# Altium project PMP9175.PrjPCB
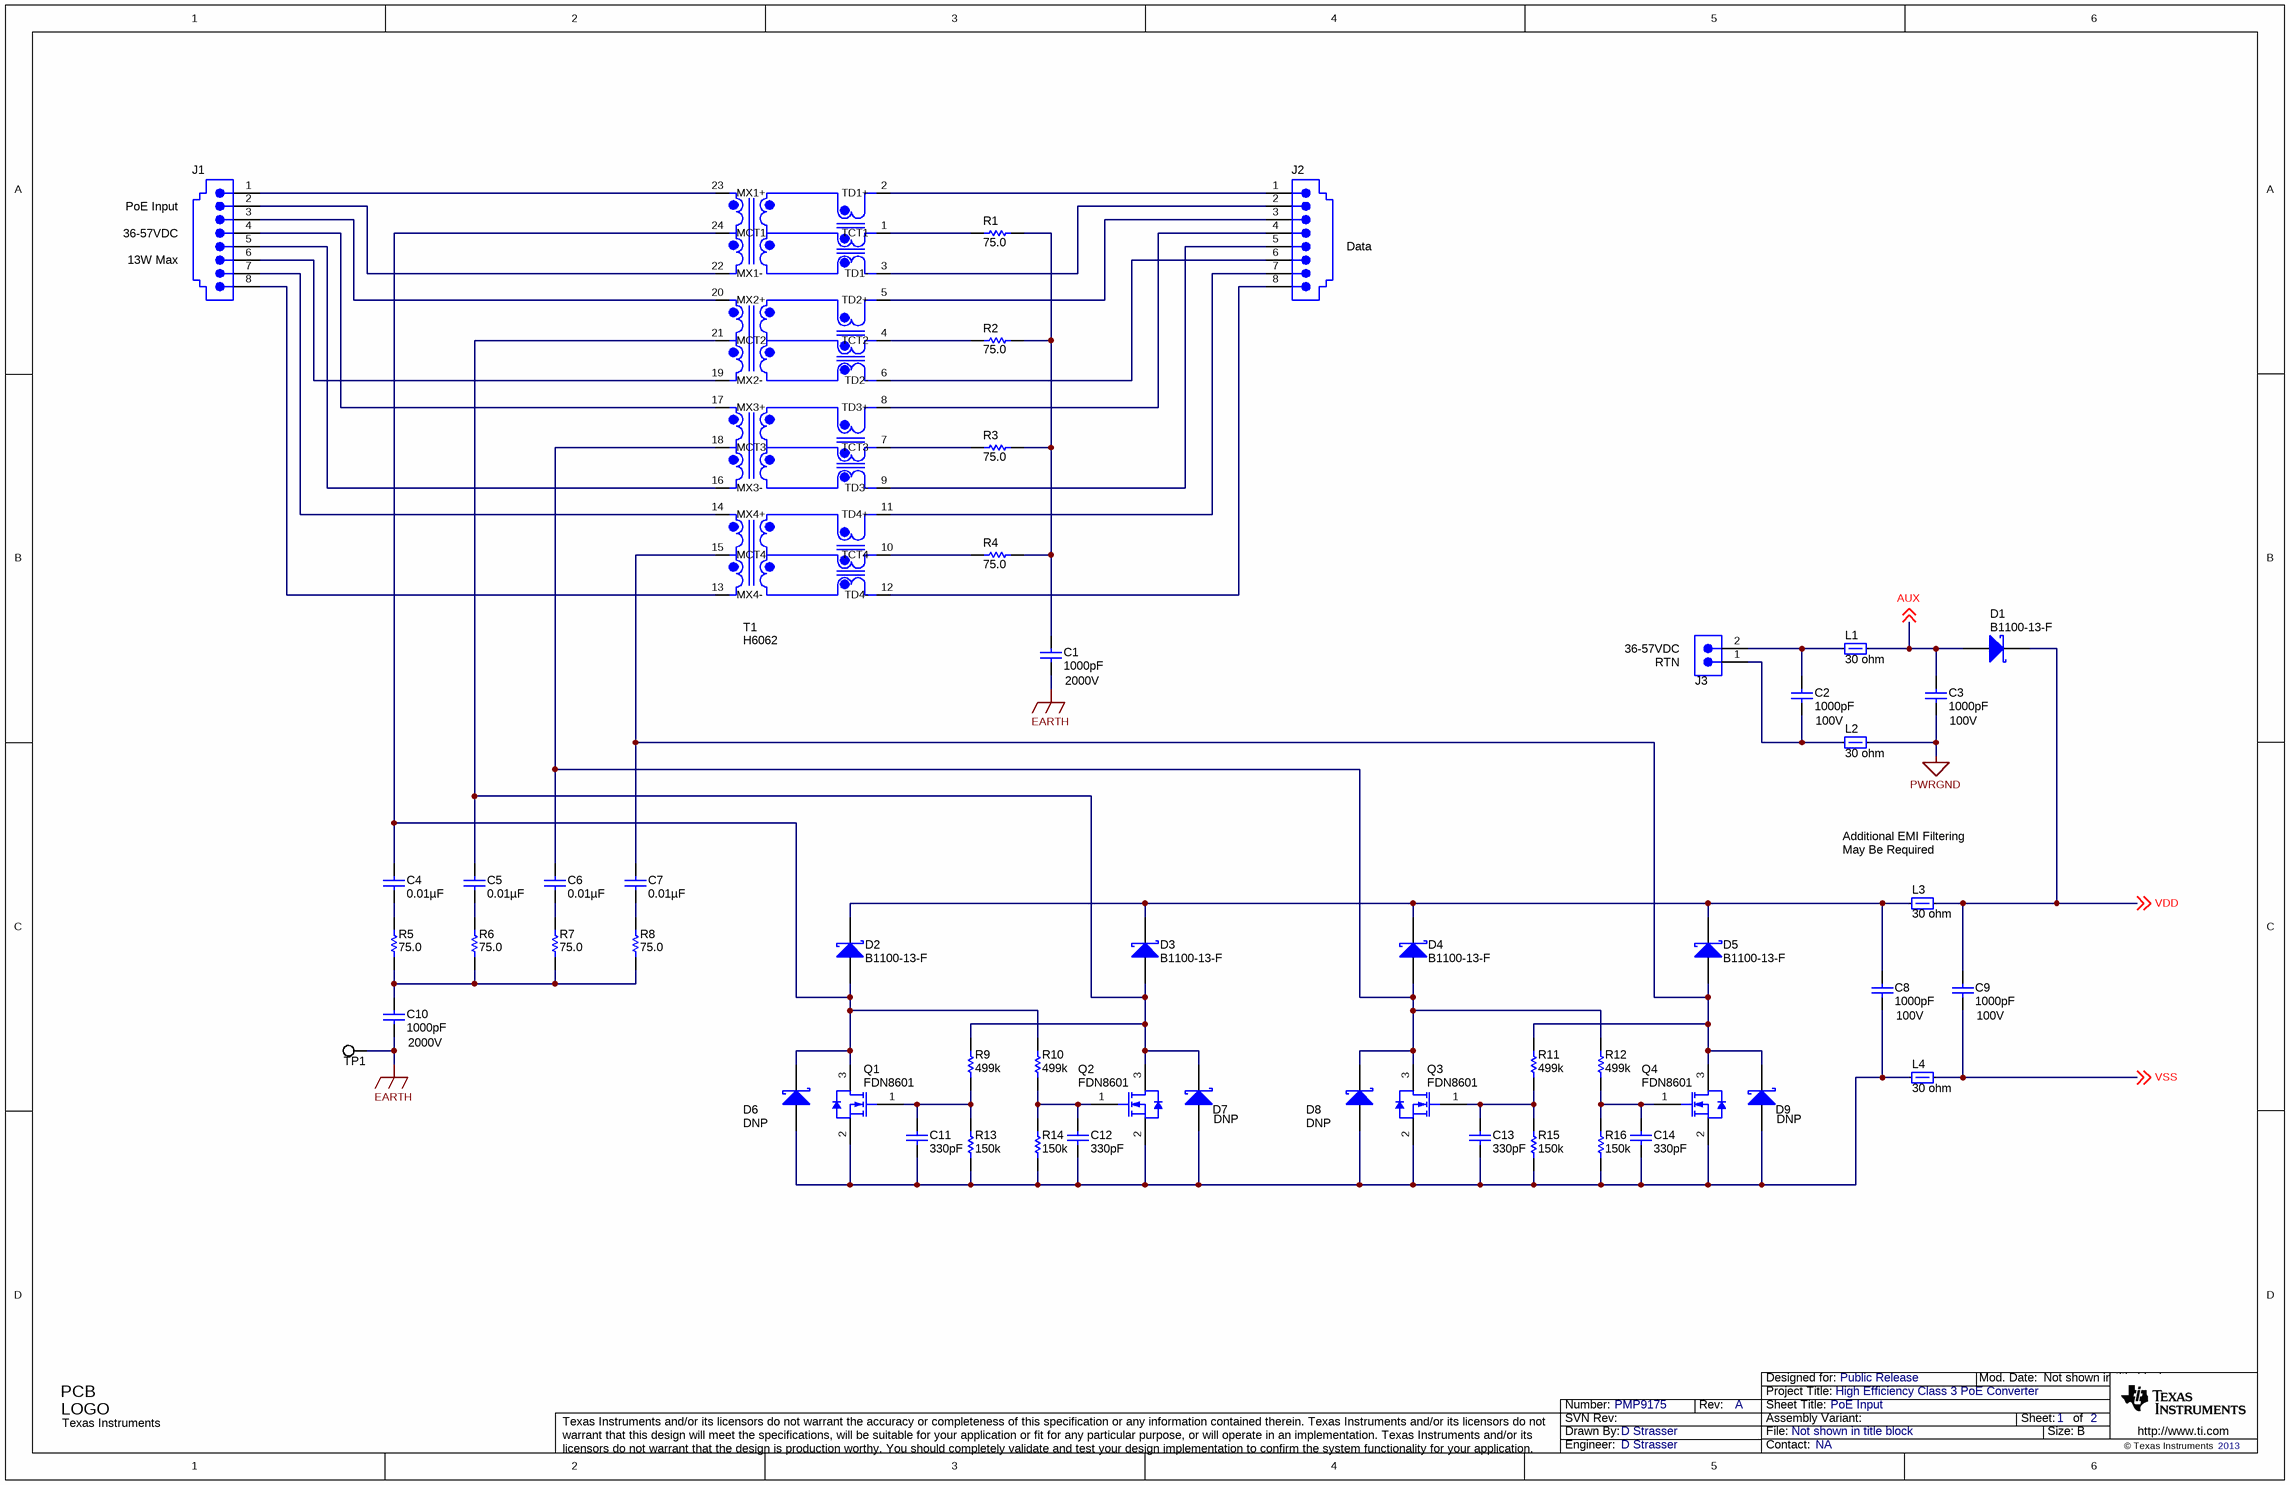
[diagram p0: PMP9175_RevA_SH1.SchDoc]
CopyrightYear: 2013; PCB_Layout: R Smith; PCB_Rev: A; PRJ_Customer: Public Release; PRJ_Engineer: D Strasser; PRJ_Number: PMP9175; PRJ_Title: High Efficiency Class 3 PoE Converter; SCH_Rev: A; TechSupport: NA
2 sheets, 114 parts. Net scope: global (net labels, ports and power ports of the same name join across sheets).
Board file: PMP9175_RevA.PcbDoc
Sheets:
  PMP9175_RevA_SH1.SchDoc
  PMP9175_RevA_SH2.SchDoc

## Sheet PMP9175_RevA_SH1.SchDoc: PoE Input
size 431 x 279 mm; Date: Not shown in title block; ApprovedBy: Not shown in title block; CheckedBy: Not shown in title block; Author: Not shown in title block; CompanyName: Not shown in title block; DrawnBy: D Strasser; Engineer: Not shown in title block; Organization: Not shown in title block; Address1: Not shown in title block; Address2: Not shown in title block; Address3: Not shown in title block; Address4: Not shown in title block; DocumentNumber: 1; Revision: Use project parameter SCH_Rev; SheetNumber: 1; SheetTotal: 2; PageSetup: Record=PageOptions|CenterHorizontal=True|CenterVertical=True|PrintScale=1.00|XCorrection=1.00|YCorrection=1.00|PrintKind=0|BorderSize=5000000|LeftOffset=0|BottomOffset=0|Orientation=2|PaperLength=1000|PaperWidth=1000|Scale=100|PaperSource=15|PrintQuality=600|MediaType=1|DitherType=10|PaperKind=Letter|PrintScaleMode=1

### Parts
C1  ValueDisplayed: 1000pF  Value2: 2000V  [1812]  (hidden comment: 1812GC102KA1)
C2  ValueDisplayed: 1000pF  Value2: 100V  [0603]  (hidden comment: C1608X7R2A102K)
C3  ValueDisplayed: 1000pF  Value2: 100V  [0603]  (hidden comment: C1608X7R2A102K)
C4  ValueDisplayed: 0.01µF  [0603]  (hidden comment: C1608X7R2A103K)
C5  ValueDisplayed: 0.01µF  [0603]  (hidden comment: C1608X7R2A103K)
C6  ValueDisplayed: 0.01µF  [0603]  (hidden comment: C1608X7R2A103K)
C7  ValueDisplayed: 0.01µF  [0603]  (hidden comment: C1608X7R2A103K)
C8  ValueDisplayed: 1000pF  Value2: 100V  [0603]  (hidden comment: C1608X7R2A102K)
C9  ValueDisplayed: 1000pF  Value2: 100V  [0603]  (hidden comment: C1608X7R2A102K)
C10  ValueDisplayed: 1000pF  Value2: 2000V  [1812]  (hidden comment: 1812GC102KA1)
C11  ValueDisplayed: 330pF  [0603]  (hidden comment: C1608C0G1H331J)
C12  ValueDisplayed: 330pF  [0603]  (hidden comment: C1608C0G1H331J)
C13  ValueDisplayed: 330pF  [0603]  (hidden comment: C1608C0G1H331J)
C14  ValueDisplayed: 330pF  [0603]  (hidden comment: C1608C0G1H331J)
D1  B1100-13-F  [SMA]
D2  B1100-13-F  [SMA]
D3  B1100-13-F  [SMA]
D4  B1100-13-F  [SMA]
D5  B1100-13-F  [SMA]
D6  value DNP  [SMA]  (hidden comment: B1100-13-F)
D7  value DNP  [SMA]  (hidden comment: B1100-13-F)
D8  value DNP  [SMA]  (hidden comment: B1100-13-F)
D9  value DNP  [SMA]  (hidden comment: B1100-13-F)
J1  1-406541-1  [1-406541-1]  (value not drawn)
J2  1-406541-1  [1-406541-1]  (value not drawn)
J3  ED555/2DS  [TERM_BLK_ED555-2DS]  (value not drawn)
L1  value 30 ohm  [0805_HV]  (hidden comment: MMZ2012R300A)
L2  value 30 ohm  [0805_HV]  (hidden comment: MMZ2012R300A)
L3  value 30 ohm  [0805_HV]  (hidden comment: MMZ2012R300A)
L4  value 30 ohm  [0805_HV]  (hidden comment: MMZ2012R300A)
Logo1  Texas Instruments  [TI_Stacked_Overlay_Small]  (no BOM)
Q1  FDN8601  [SSOT-3]
Q2  FDN8601  [SSOT-3]
Q3  FDN8601  [SSOT-3]
Q4  FDN8601  [SSOT-3]
R1  value 75.0  [0603]  (hidden comment: CRCW060375R0FKEA)
R2  value 75.0  [0603]  (hidden comment: CRCW060375R0FKEA)
R3  value 75.0  [0603]  (hidden comment: CRCW060375R0FKEA)
R4  value 75.0  [0603]  (hidden comment: CRCW060375R0FKEA)
R5  value 75.0  [0603]  (hidden comment: CRCW060375R0FKEA)
R6  value 75.0  [0603]  (hidden comment: CRCW060375R0FKEA)
R7  value 75.0  [0603]  (hidden comment: CRCW060375R0FKEA)
R8  value 75.0  [0603]  (hidden comment: CRCW060375R0FKEA)
R9  value 499k  [0603]  (hidden comment: CRCW0603499KFKEA)
R10  value 499k  [0603]  (hidden comment: CRCW0603499KFKEA)
R11  value 499k  [0603]  (hidden comment: CRCW0603499KFKEA)
R12  value 499k  [0603]  (hidden comment: CRCW0603499KFKEA)
R13  value 150k  [0603]  (hidden comment: CRCW0603150KFKEA)
R14  value 150k  [0603]  (hidden comment: CRCW0603150KFKEA)
R15  value 150k  [0603]  (hidden comment: CRCW0603150KFKEA)
R16  value 150k  [0603]  (hidden comment: CRCW0603150KFKEA)
T1  H6062  [S0-24_500MIL]
TP1  5012  [Keystone5012]  (value not drawn)

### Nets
EARTH: C1.2 C10.2 TP1.1
PWRGND: C3.2 L2.2
AUX: C3.1 D1.2(A) L1.2 ; off-sheet AUX
VDD: C9.1 D1.1(K) L3.2 ; off-sheet VDD
VSS: C9.2 L4.2 ; off-sheet VSS
NetC1_1: C1.1 R1.2 R2.2 R3.2 R4.2
NetC2_1: C2.1 J3.2 L1.1
NetC2_2: C2.2 J3.1 L2.1
NetC4_1: C4.1 D2.2(A) D6.1(K) Q1.3(D) R10.2 T1.24(MCT1)
NetC4_2: C4.2 R5.2
NetC5_1: C5.1 D3.2(A) D7.1(K) Q2.3(D) R9.2 T1.21(MCT2)
NetC5_2: C5.2 R6.2
NetC6_1: C6.1 D4.2(A) D8.1(K) Q3.3(D) R12.2 T1.18(MCT3)
NetC6_2: C6.2 R7.2
NetC7_1: C7.1 D5.2(A) D9.1(K) Q4.3(D) R11.2 T1.15(MCT4)
NetC7_2: C7.2 R8.2
NetC8_1: C8.1 D2.1(K) D3.1(K) D4.1(K) D5.1(K) L3.1
NetC8_2: C8.2 C11.2 C12.2 C13.2 C14.2 D6.2(A) D7.2(A) D8.2(A) D9.2(A) L4.1 Q1.2(S) Q2.2(S) Q3.2(S) Q4.2(S) R13.1 R14.1 R15.1 R16.1
NetC10_1: C10.1 R5.1 R6.1 R7.1 R8.1
NetC11_1: C11.1 Q1.1(G) R9.1 R13.2
NetC12_1: C12.1 Q2.1(G) R10.1 R14.2
NetC13_1: C13.1 Q3.1(G) R11.1 R15.2
NetC14_1: C14.1 Q4.1(G) R12.1 R16.2
NetJ1_1: J1.1 T1.23(MX1+)
NetJ1_2: J1.2 T1.22(MX1-)
NetJ1_3: J1.3 T1.20(MX2+)
NetJ1_4: J1.4 T1.17(MX3+)
NetJ1_5: J1.5 T1.16(MX3-)
NetJ1_6: J1.6 T1.19(MX2-)
NetJ1_7: J1.7 T1.14(MX4+)
NetJ1_8: J1.8 T1.13(MX4-)
NetJ2_1: J2.1 T1.2(TD1+)
NetJ2_2: J2.2 T1.3(TD1-)
NetJ2_3: J2.3 T1.5(TD2+)
NetJ2_4: J2.4 T1.8(TD3+)
NetJ2_5: J2.5 T1.9(TD3-)
NetJ2_6: J2.6 T1.6(TD2-)
NetJ2_7: J2.7 T1.11(TD4+)
NetJ2_8: J2.8 T1.12(TD4-)
NetR1_1: R1.1 T1.1(TCT1)
NetR2_1: R2.1 T1.4(TCT2)
NetR3_1: R3.1 T1.7(TCT3)
NetR4_1: R4.1 T1.10(TCT4)

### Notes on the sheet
- PoE Input
- 36-57VDC
- 13W Max
- Data
- (near J3) 36-57VDC
- (near J3) RTN
- Additional EMI Filtering
- (near L3) May Be Required

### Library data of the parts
C1 C10 = 1812GC102KA1: CAP, CERM, 1000pF, 2000V, +/-10%, X7R, 1812; Manufacturer: AVX; Polarized: N; CompType: Capacitor; U/M: EA; Cap_F: 0.000000001; Tolerance_%: 10; Value1: Unknown; VDC_V: 2000; TaMin_C: -55; TaMax_C: 125
C2 C3 C8 C9 = C1608X7R2A102K: CAP, CERM, 1000pF, 100V, +/-10%, X7R, 0603; Manufacturer: TDK; Polarized: N; CompType: Capacitor; U/M: EA; Cap_F: 0.000000001; Tolerance_%: 10; ESR_Ohm: 0.2494; Value1: 0.2494 ohm; VDC_V: 100; TaMin_C: -55; TaMax_C: 125
C4-C7 = C1608X7R2A103K: CAP, CERM, 0.01uF, 100V, +/-10%, X7R, 0603; Manufacturer: TDK; Polarized: N; CompType: Capacitor; U/M: EA; Cap_F: 0.00000001; Tolerance_%: 10; ESR_Ohm: 0.0661; Value1: 0.0661 ohm; VDC_V: 100; TaMin_C: -55; TaMax_C: 125
C11-C14 = C1608C0G1H331J: CAP, CERM, 330pF, 50V, +/-5%, C0G/NP0, 0603; Manufacturer: TDK; Polarized: N; CompType: Capacitor; U/M: EA; Cap_F: 0.00000000033; Tolerance_%: 5; ESR_Ohm: 0.1096; Value1: 0.1096 ohm; VDC_V: 50; TaMin_C: -55; TaMax_C: 125
D1-D9 = B1100-13-F: Diode, Schottky, 100V, 1A, SMA; Manufacturer: Diodes Inc.; U/M: EA; Vf_V: 0.79; Value2: 0.79V; Io_A: 1; Vr_V: 100; TJmax_C: 150; RJC_CperW: 25
J1 J2 = 1-406541-1: RJ-45, Right Angle, No LED, tab up; Manufacturer: AMP; SymbolCreator: a0799628; CompType: Connector; U/M: EA
J3 = ED555/2DS: Terminal Block, 6A, 3.5mm Pitch, 2-Pos, TH; Manufacturer: On-Shore Technology; SymbolCreator: a0412235; CompType: Connector; U/M: EA
L1-L4 = MMZ2012R300A: 1.5A Ferrite Bead, 30 ohm @ 100MHz, SMD; Manufacturer: TDK; Imax_A: 1.5; Irms: 1.5A @ C rise; Isat: 1.5A @ % inductance drop; DCR_ohm: 0.05; Value1: 0.05 ohm; ZTyp@100MHz_Ohm: 30; U/M: EA
Logo1 = TI_Logo: Texas Instrument Corporate Signature; SymbolCreator: codlsc
Q1-Q4 = FDN8601: MOSFET, N-CH, 100V, 2.7A, SSOT-3; Manufacturer: Fairchild Semiconductor; Alternate Manufacturer: None; U/M: EA; ChType: N; VdsMax_V: 100; Value1: ? ohm; Rdson45_Ohm: 0; Value2: 3 nC; QgTyp_nC: 3; Vgs_V: 20; IdsMax_A: 2.7
R1-R8 = CRCW060375R0FKEA: RES, 75.0 ohm, 1%, 0.1W, 0603; Manufacturer: Vishay-Dale; CompType: Resistor; Res_ohm: 75; Value_Code: 75R0; Tolerance_%: 1; Power_W: 0.1; TempCo: 100 ppm/C; EIA_Code: E96; U/M: EA
R9-R12 = CRCW0603499KFKEA: RES, 499k ohm, 1%, 0.1W, 0603; Manufacturer: Vishay-Dale; CompType: Resistor; Res_ohm: 499000; Tolerance_%: 1; Power_W: 0.1; VDC_V: 75; TempCo: 100 ppm/C; EIA_Code: E96; U/M: EA
R13-R16 = CRCW0603150KFKEA: RES, 150k ohm, 1%, 0.1W, 0603; Manufacturer: Vishay-Dale; CompType: Resistor; Res_ohm: 150000; Tolerance_%: 1; Power_W: 0.1; VDC_V: 75; TempCo: 100 ppm/C; EIA_Code: E96; U/M: EA
T1 = XFMR_H6062: Transformer,; Manufacturer: Pulse; Area: 496,8; Value: {Value}
TP1 = 5012: Test Point, Multipurpose, White, TH; Manufacturer: Keystone; CompType: Test Point Loop; U/M: EA

## Sheet PMP9175_RevA_SH2.SchDoc: Isolated Flyback Converter, 5V/2A
size 431 x 279 mm; Date: Not shown in title block; ApprovedBy: Not shown in title block; CheckedBy: Not shown in title block; Author: Not shown in title block; CompanyName: Not shown in title block; DrawnBy: D Strasser; Engineer: Not shown in title block; Organization: Not shown in title block; Address1: Not shown in title block; Address2: Not shown in title block; Address3: Not shown in title block; Address4: Not shown in title block; DocumentNumber: 2; Revision: Use project parameter SCH_Rev; SheetNumber: 2; SheetTotal: 2; PageSetup: Record=PageOptions|CenterHorizontal=True|CenterVertical=True|PrintScale=1.00|XCorrection=1.00|YCorrection=1.00|PrintKind=0|BorderSize=5000000|LeftOffset=0|BottomOffset=0|Orientation=2|PaperLength=1000|PaperWidth=1000|Scale=100|PaperSource=15|PrintQuality=600|MediaType=1|DitherType=10|PaperKind=Letter|PrintScaleMode=1
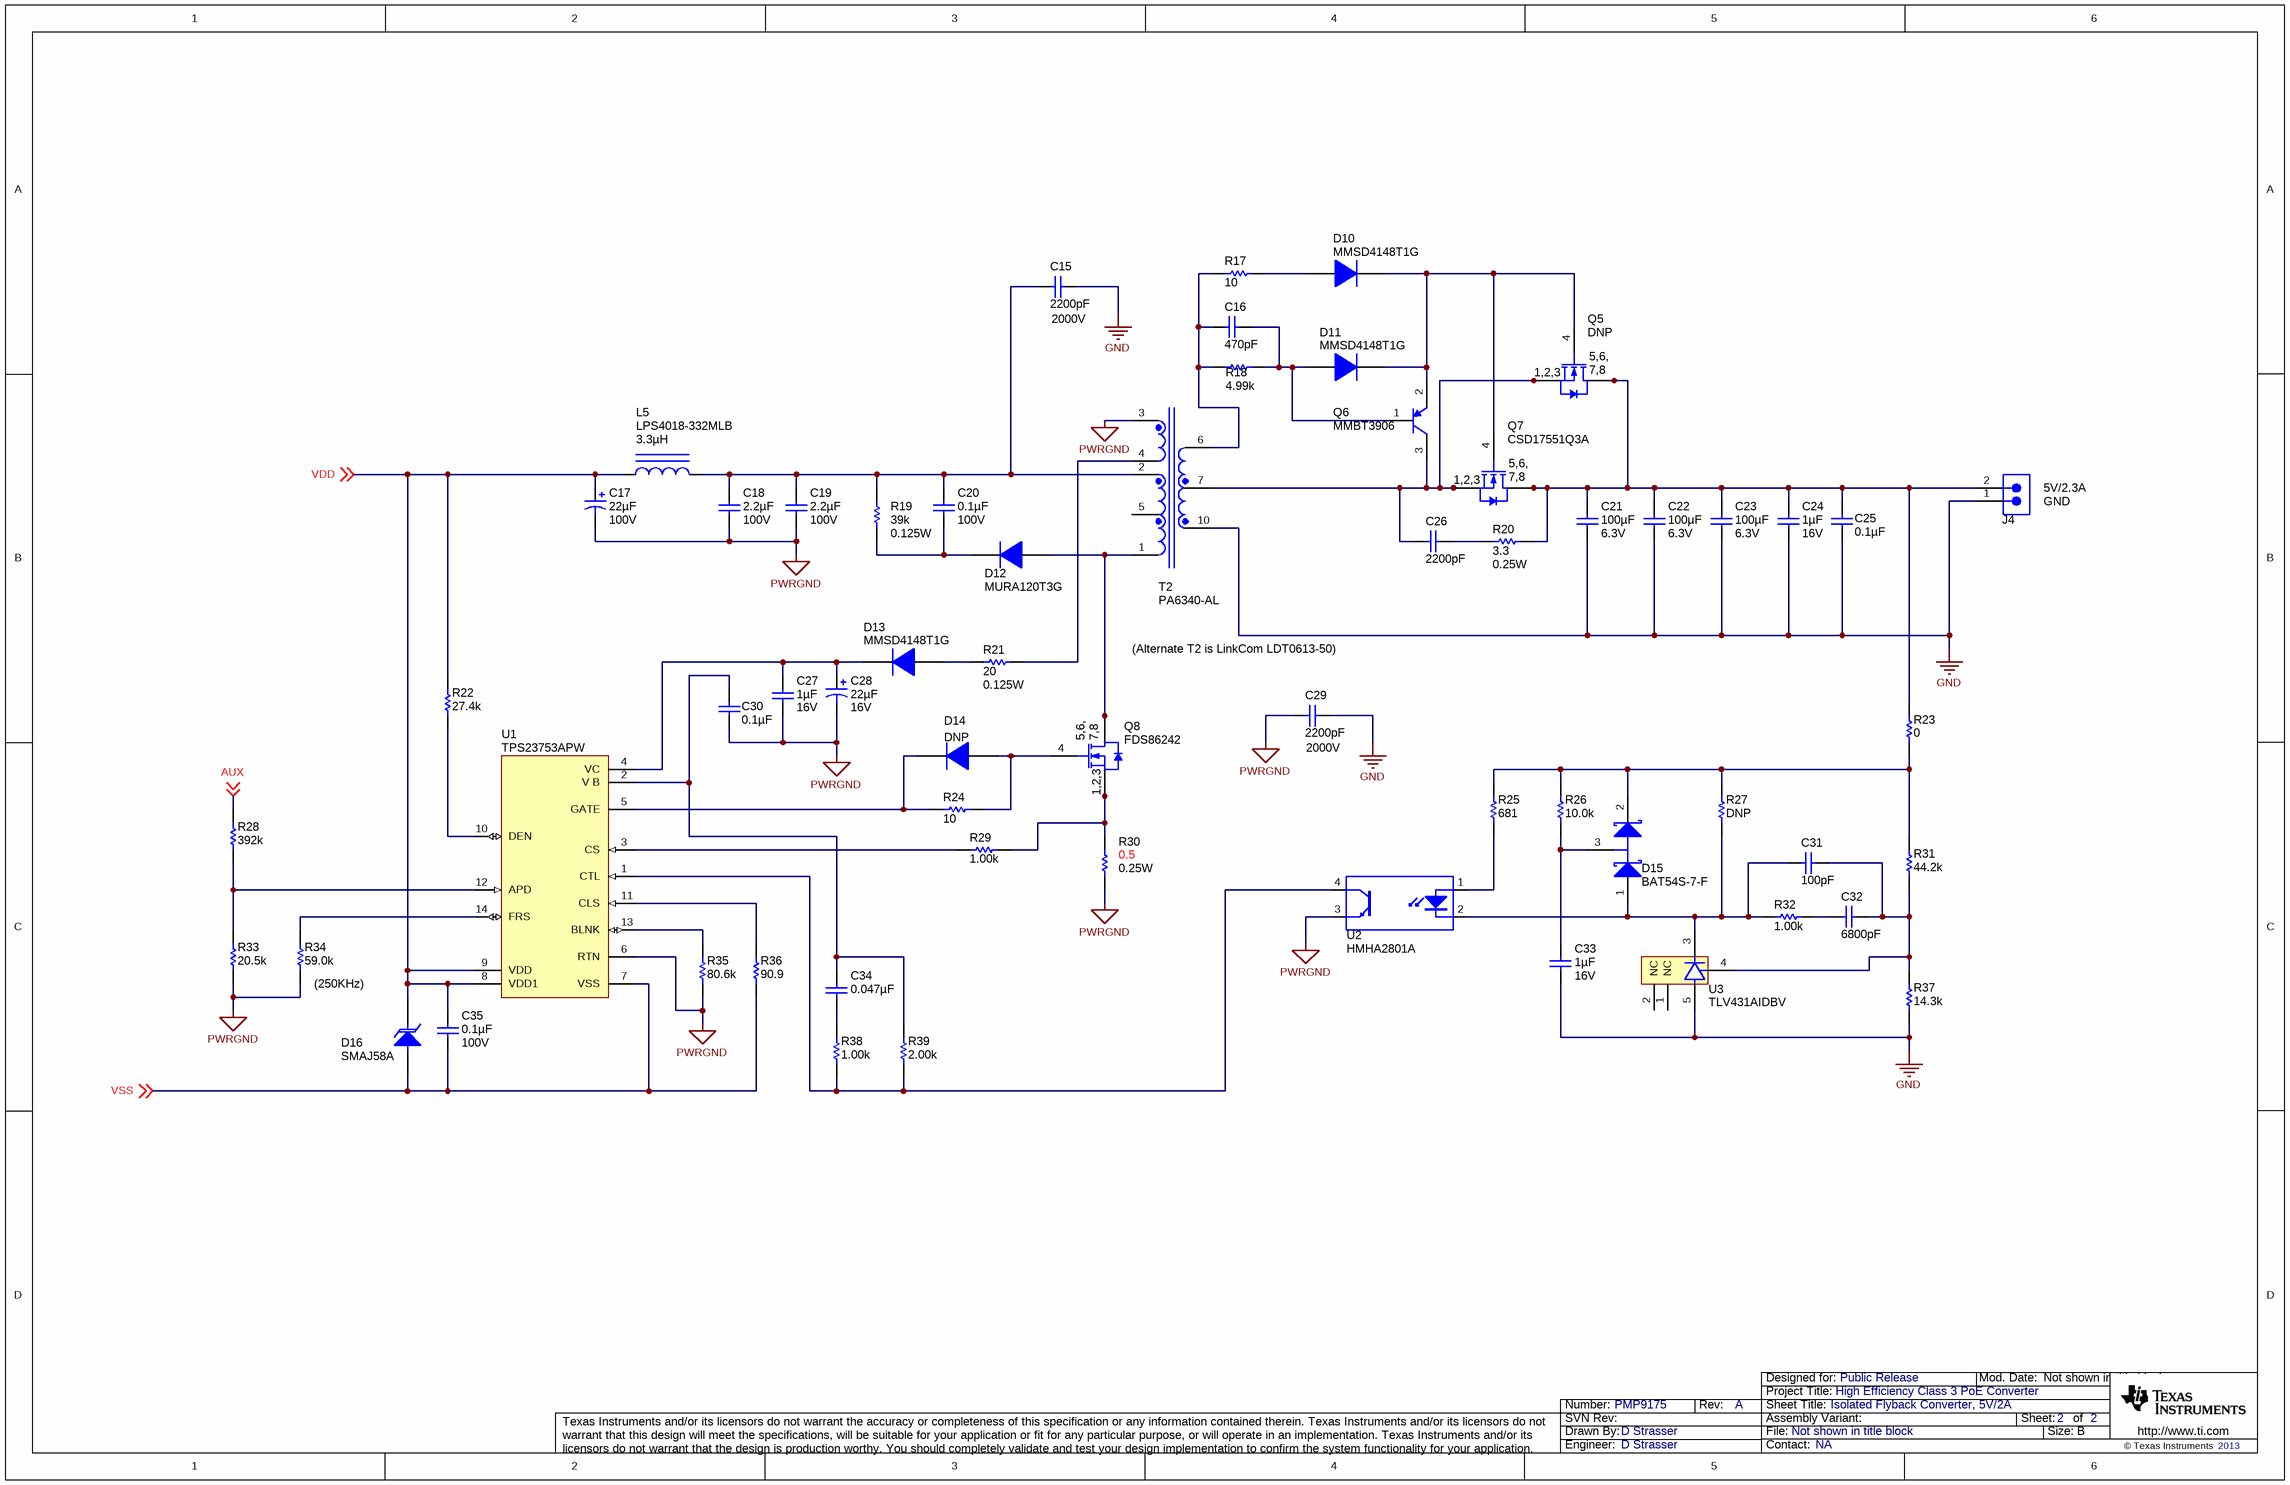
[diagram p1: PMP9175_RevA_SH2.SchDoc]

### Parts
C15  ValueDisplayed: 2200pF  Value2: 2000V  [1812]  (hidden comment: C4532X7R3D222K)
C16  ValueDisplayed: 470pF  [0603]  (hidden comment: C1608C0G1H471J)
C17  ValueDisplayed: 22µF  Value2: 100V  [SM_RADIAL_F]  (hidden comment: EEE-FK2A220P)
C18  ValueDisplayed: 2.2µF  Value2: 100V  [1210]  (hidden comment: GRM32ER72A225KA35L)
C19  ValueDisplayed: 2.2µF  Value2: 100V  [1210]  (hidden comment: GRM32ER72A225KA35L)
C20  ValueDisplayed: 0.1µF  Value2: 100V  [0805_HV]  (hidden comment: C2012X7R2A104K)
C21  ValueDisplayed: 100µF  Value2: 6.3V  [1210]  (hidden comment: C3225X5R0J107M)
C22  ValueDisplayed: 100µF  Value2: 6.3V  [1210]  (hidden comment: C3225X5R0J107M)
C23  ValueDisplayed: 100µF  Value2: 6.3V  [1210]  (hidden comment: C3225X5R0J107M)
C24  ValueDisplayed: 1µF  Value2: 16V  [0603]  (hidden comment: C1608X7R1C105K)
C25  ValueDisplayed: 0.1µF  [0603]  (hidden comment: C1608X7R1H104K)
C26  ValueDisplayed: 2200pF  [0603]  (hidden comment: C1608X7R1H222K)
C27  ValueDisplayed: 1µF  Value2: 16V  [0603]  (hidden comment: C1608X7R1C105K)
C28  ValueDisplayed: 22µF  Value2: 16V  [SM_RADIAL_C]  (hidden comment: EEE-FK1C220R)
C29  ValueDisplayed: 2200pF  Value2: 2000V  [1812]  (hidden comment: C4532X7R3D222K)
C30  ValueDisplayed: 0.1µF  [0603]  (hidden comment: C1608X7R1H104K)
C31  ValueDisplayed: 100pF  [0603]  (hidden comment: C1608C0G1H101J)
C32  ValueDisplayed: 6800pF  [0603]  (hidden comment: GRM188R71H682KA01D)
C33  ValueDisplayed: 1µF  Value2: 16V  [0603]  (hidden comment: C1608X7R1C105K)
C34  ValueDisplayed: 0.047µF  [0603]  (hidden comment: C1608X7R1E473K)
C35  ValueDisplayed: 0.1µF  Value2: 100V  [0805_HV]  (hidden comment: C2012X7R2A104K)
D10  MMSD4148T1G  [SOD-123]
D11  MMSD4148T1G  [SOD-123]
D12  MURA120T3G  [SMA]
D13  MMSD4148T1G  [SOD-123]
D14  value DNP  [SOD-123]  (hidden comment: MMSD4148T1G)
D15  BAT54S-7-F  [SOT-23]
D16  SMAJ58A  [SMA]
J4  ED555/2DS  [TERM_BLK_ED555-2DS]  (value not drawn)
L5  LPS4018-332MLB  ValueDisplayed: 3.3µH  [LPS4018]
Q5  value DNP  [TRANS_NexFET_Q5A]  (hidden comment: CSD17527Q5A)
Q6  MMBT3906  [SOT-23]
Q7  CSD17551Q3A  [TRANS_NexFET_Q3A]
Q8  FDS86242  [SOIC-8]
R17  value 10  [0603]  (hidden comment: CRCW060310R0JNEA)
R18  value 4.99k  [0603]  (hidden comment: CRCW06034K99FKEA)
R19  value 39k  Value2: 0.125W  [0805_HV]  (hidden comment: CRCW080539K0JNEA)
R20  value 3.3  Value2: 0.25W  [1206]  (hidden comment: CRCW12063R30JNEA)
R21  value 20  Value2: 0.125W  [0805_HV]  (hidden comment: CRCW080520R0JNEA)
R22  value 27.4k  [0603]  (hidden comment: CRCW060327K4FKEA)
R23  value 0  [0603]  (hidden comment: ERJ-3GEY0R00V)
R24  value 10  [0603]  (hidden comment: CRCW060310R0JNEA)
R25  value 681  [0603]  (hidden comment: CRCW0603681RFKEA)
R26  value 10.0k  [0603]  (hidden comment: CRCW060310K0FKEA)
R27  value DNP  [0603]  (hidden comment: CRCW06032K00FKEA)
R28  value 392k  [0603]  (hidden comment: CRCW0603392KFKEA)
R29  value 1.00k  [0603]  (hidden comment: CRCW06031K00FKEA)
R30  value 0.5  Value2: 0.25W  [1206]  (hidden comment: STD)
R31  value 44.2k  [0603]  (hidden comment: CRCW060344K2FKEA)
R32  value 1.00k  [0603]  (hidden comment: CRCW06031K00FKEA)
R33  value 20.5k  [0603]  (hidden comment: CRCW060320K5FKEA)
R34  value 59.0k  [0603]  (hidden comment: CRCW060359K0FKEA)
R35  value 80.6k  [0603]  (hidden comment: CRCW060380K6FKEA)
R36  value 90.9  [0603]  (hidden comment: CRCW060390R9FKEA)
R37  value 14.3k  [0603]  (hidden comment: CRCW060314K3FKEA)
R38  value 1.00k  [0603]  (hidden comment: CRCW06031K00FKEA)
R39  value 2.00k  [0603]  (hidden comment: CRCW06032K00FKEA)
T2  PA6340-AL  [Coilcraft_PA6340-AL]
U1  TPS23753APW  [PW0014A_N]
U2  HMHA2801A  [MFP04A]
U3  TLV431AIDBV  [DBV0005A_N]

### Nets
GND: C15.1 C21.2 C22.2 C23.2 C24.2 C25.2 C29.1 C33.2 J4.1 R37.1 T2.10 U3.5(A)
PWRGND: C17.2(-) C18.2 C19.2 C27.2 C28.2(-) C29.2 C30.2 R30.1 R33.1 R34.1 R35.1 T2.3 U1.6(RTN) U2.3(E)
AUX: R28.2 ; off-sheet AUX
VDD: C17.1(+) C35.1 D16.1(K) L5.1 R22.2 U1.8(VDD1) U1.9(VDD) ; off-sheet VDD
VSS: C35.2 D16.2(A) R36.1 U1.7(VSS) ; off-sheet VSS
NetC15_2: C15.2 C18.1 C19.1 C20.1 L5.2 R19.2 T2.2
NetC16_1: C16.1 D11.2(A) Q6.1(B) R18.2
NetC16_2: C16.2 R17.1 R18.1 T2.6
NetC20_2: C20.2 D12.1(K) R19.1
NetC21_1: C21.1 C22.1 C23.1 C24.1 C25.1 J4.2 Q5.5(D) Q5.6(D) Q5.7(D) Q5.8(D) Q5.9(D) Q7.5(D) Q7.6(D) Q7.7(D) Q7.8(D) Q7.9(D) R20.2 R23.2
NetC26_1: C26.1 R20.1
NetC26_2: C26.2 Q5.1(S) Q5.2(S) Q5.3(S) Q6.3(C) Q7.1(S) Q7.2(S) Q7.3(S) T2.7
NetC27_1: C27.1 C28.1(+) D13.1(K) U1.4(VC)
NetC30_1: C30.1 C34.1 R39.2 U1.2(V_B)
NetC31_1: C31.1 C32.1 R31.1 R37.2 U3.4(REF)
NetC31_2: C31.2 D15.1(A) R27.1 R32.2 U2.2(K) U3.3(C)
NetC32_2: C32.2 R32.1
NetC33_1: C33.1 D15.3(C) R26.1
NetC34_2: C34.2 R38.2
NetD10_1: D10.1(K) D11.1(K) Q5.4(G) Q6.2(E) Q7.4(G)
NetD10_2: D10.2(A) R17.2
NetD12_2: D12.2(A) Q8.5(D) Q8.6(D) Q8.7(D) Q8.8(D) T2.1
NetD13_2: D13.2(A) R21.1
NetD14_1: D14.1(K) R24.1 U1.5(GATE)
NetD14_2: D14.2(A) Q8.4(G) R24.2
NetD15_2: D15.2(K) R23.1 R25.2 R26.2 R27.2 R31.2
NetQ8_1: Q8.1(S) Q8.2(S) Q8.3(S) R29.2 R30.2
NetR21_2: R21.2 T2.4
NetR22_1: R22.1 U1.10(DEN)
NetR25_1: R25.1 U2.1(A)
NetR28_1: R28.1 R33.2 U1.12(APD)
NetR29_1: R29.1 U1.3(CS)
NetR34_2: R34.2 U1.14(FRS)
NetR35_2: R35.2 U1.13(BLNK)
NetR36_2: R36.2 U1.11(CLS)
NetR38_1: R38.1 R39.1 U1.1(CTL) U2.4(C)

Not connected (* = marked no-connect by the designer): T2 5; U3 1(NC) 2(NC)

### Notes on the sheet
- (near J4) 5V/2.3A
- (near J4) GND
- (Alternate T2 is LinkCom LDT0613-50)
- (near R34) (250KHz)

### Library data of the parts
C15 C29 = C4532X7R3D222K: CAP, CERM, 2200pF, 2000V, +/-10%, X7R, 1812; Manufacturer: TDK; Polarized: N; CompType: Capacitor; U/M: EA; Cap_F: 0.0000000022; Tolerance_%: 10; Value1: Unknown; VDC_V: 2000; TaMin_C: -55; TaMax_C: 125
C16 = C1608C0G1H471J: CAP, CERM, 470pF, 50V, +/-5%, C0G/NP0, 0603; Manufacturer: TDK; Polarized: N; CompType: Capacitor; U/M: EA; Cap_F: 0.00000000047; Tolerance_%: 5; ESR_Ohm: 0.0922; Value1: 0.0922 ohm; VDC_V: 50; TaMin_C: -55; TaMax_C: 125
C17 = EEE-FK2A220P: CAP, AL, 22uF, 100V, +/-20%, 1.3 ohm, SMD; Manufacturer: Panasonic; Polarized: Y; CompType: Capacitor; U/M: EA; Cap_F: 0.000022; Tolerance_%: 20; Value1: 1.3 ohm; VDC_V: 100; ESR_Ohm: 1.3; IRMS_A: 0.13; TaMin_C: -55; TaMax_C: 105; Cap_Case: F
C18 C19 = GRM32ER72A225KA35L: CAP, CERM, 2.2uF, 100V, +/-10%, X7R, 1210; Manufacturer: MuRata; Polarized: N; CompType: Capacitor; U/M: EA; Cap_F: 0.0000022; Tolerance_%: 10; ESR_Ohm: 0.007; Value1: 0.007 ohm; VDC_V: 100; IRMS_A: 4.4; TaMin_C: -55; TaMax_C: 125
C20 C35 = C2012X7R2A104K: CAP, CERM, 0.1uF, 100V, +/-10%, X7R, 0805; Manufacturer: TDK; Polarized: N; CompType: Capacitor; U/M: EA; Cap_F: 0.0000001; Tolerance_%: 10; ESR_Ohm: 0.0158; Value1: 0.0158 ohm; VDC_V: 100; TaMin_C: -55; TaMax_C: 125; Cap_Case: 0805
C21-C23 = C3225X5R0J107M: CAP, CERM, 100uF, 6.3V, +/-20%, X5R, 1210; Manufacturer: TDK; Polarized: N; CompType: Capacitor; U/M: EA; Cap_F: 0.0001; Tolerance_%: 20; ESR_Ohm: 0.002; Value1: 0.002 ohm; VDC_V: 6.3; IRMS_A: 3.5; TaMin_C: -55; TaMax_C: 85
C24 C27 C33 = C1608X7R1C105K: CAP, CERM, 1uF, 16V, +/-10%, X7R, 0603; Manufacturer: TDK; Polarized: N; CompType: Capacitor; U/M: EA; Cap_F: 0.000001; Tolerance_%: 10; ESR_Ohm: 0.0057; Value1: 0.0057 ohm; VDC_V: 16; TaMin_C: -55; TaMax_C: 125
C25 C30 = C1608X7R1H104K: CAP, CERM, 0.1uF, 50V, +/-10%, X7R, 0603; Manufacturer: TDK; Polarized: N; CompType: Capacitor; U/M: EA; Cap_F: 0.0000001; Tolerance_%: 10; ESR_Ohm: 0.017; Value1: 0.017 ohm; VDC_V: 50; TaMin_C: -55; TaMax_C: 125
C26 = C1608X7R1H222K: CAP, CERM, 2200pF, 50V, +/-10%, X7R, 0603; Manufacturer: TDK; Polarized: N; CompType: Capacitor; U/M: EA; Cap_F: 0.0000000022; Tolerance_%: 10; ESR_Ohm: 0.145; Value1: 0.145 ohm; VDC_V: 50; TaMin_C: -55; TaMax_C: 125
C28 = EEE-FK1C220R: CAP, AL, 22uF, 16V, +/-20%, 0.7 ohm, SMD; Manufacturer: Panasonic; Polarized: Y; CompType: Capacitor; U/M: EA; Cap_F: 0.000022; Tolerance_%: 20; Value1: 0.7 ohm; VDC_V: 16; ESR_Ohm: 0.7; IRMS_A: 0.16; TaMin_C: -55; TaMax_C: 105; Cap_Case: C
C31 = C1608C0G1H101J: CAP, CERM, 100pF, 50V, +/-5%, C0G/NP0, 0603; Manufacturer: TDK; Polarized: N; CompType: Capacitor; U/M: EA; Cap_F: 0.0000000001; Tolerance_%: 5; ESR_Ohm: 0.1679; Value1: 0.1679 ohm; VDC_V: 50; TaMin_C: -55; TaMax_C: 125
C32 = GRM188R71H682KA01D: CAP, CERM, 6800pF, 50V, +/-10%, X7R, 0603; Manufacturer: MuRata; Polarized: N; CompType: Capacitor; U/M: EA; Cap_F: 0.0000000068; Tolerance_%: 10; Value1: Unknown; VDC_V: 50; TaMin_C: -55; TaMax_C: 125
C34 = C1608X7R1E473K: CAP, CERM, 0.047uF, 25V, +/-10%, X7R, 0603; Manufacturer: TDK; Polarized: N; CompType: Capacitor; U/M: EA; Cap_F: 0.000000047; Tolerance_%: 10; ESR_Ohm: 0.0234; Value1: 0.0234 ohm; VDC_V: 25; TaMin_C: -55; TaMax_C: 125
D10 D11 D13 D14 = MMSD4148T1G: Diode, Switching, 100V, 0.2A, SOD-123; Manufacturer: ON Semiconductor; U/M: EA; Vf_V: 1; Value2: 1V; Io_A: 0.2; Vr_V: 100; TJmax_C: 150
D12 = MURA120T3G: Diode, Ultrafast, 200V, 1A, SMA; Manufacturer: ON Semiconductor; U/M: EA; Vf_V: 0.0875; Value2: 0.0875V; Io_A: 1; Vr_V: 200; TJmax_C: 175
D15 = BAT54S-7-F: Diode, Schottky, 30V, 0.2A, SOT-23; Manufacturer: Diodes Inc.; U/M: EA; Vf_V: 0.65; Value2: 0.65V; Io_A: 0.2; Vr_V: 30; TJmax_C: 125
D16 = SMAJ58A: Diode, TVS, Uni, 58V, 400W, SMA; Manufacturer: Diodes Inc.; U/M: EA; Power_W: 400; Vr_V: 58
J4 = ED555/2DS: as J3 on sheet PMP9175_RevA_SH1
L5 = LPS4018-332MLB: Inductor, Shielded Drum Core, Ferrite, 3.3uH, 1.9A, 0.08 ohm, SMD; Manufacturer: Coilcraft; Ind_H: 3.3E-6; Imax_A: 1.9; Irms: 1.9A @ 40C rise; Isat: 2A @ 30% inductance drop; DCR_ohm: 0.08; U/M: EA
Q5 = CSD17527Q5A: MOSFET, N-CH, 30V, 65A, SON 5x6mm; Manufacturer: Texas Instruments; Alternate Manufacturer: None; U/M: EA; ChType: N; VdsMax_V: 30; Value1: 0.0125 ohm; Rdson45_Ohm: 0.0125; Value2: 2.8 nC; QgTyp_nC: 2.8; Vgs_V: 20; IdsMax_A: 65
Q6 = MMBT3906, Fairchild Semiconductor: Transistor, PNP, 40V, 0.2A, SOT-23; CompType: BJT; PNP: 1; NPN: 0; Vceo_V: 40; Vcesat1_V: 0.25; Value: 0.25V; IcRated_A: 0.2; HfeMax: 300; TaMin_C: -55; TaMax_C: 150; U/M: EA
Q7 = CSD17551Q3A: MOSFET, N-CH, 30V, 12A, SON 3.3x3.3mm; Manufacturer: Texas Instruments; Alternate Manufacturer: None; U/M: EA; ChType: N; VdsMax_V: 30; Value1: 11.8 ohm; Rdson45_Ohm: 11.8; Value2: 6 nC; QgTyp_nC: 6; Vgs_V: 20; IdsMax_A: 12
Q8 = FDS86242: MOSFET, N-CH, 150V, 4.1A, SOIC-8; Manufacturer: Fairchild Semiconductor; Alternate Manufacturer: None; U/M: EA; ChType: N; VdsMax_V: 150; Value1: 0.067 ohm; Rdson45_Ohm: 0.067; Value2: 13 nC; QgTyp_nC: 13; Vgs_V: 4; IdsMax_A: 4.1
R17 R24 = CRCW060310R0JNEA: RES, 10 ohm, 5%, 0.1W, 0603; Manufacturer: Vishay-Dale; CompType: Resistor; Value_Code: 10R0; Tolerance_%: 5; Power_W: 0.1; VDC_V: 75; TempCo: 200 ppm/C; EIA_Code: E24; U/M: EA
R18 = CRCW06034K99FKEA: RES, 4.99k ohm, 1%, 0.1W, 0603; Manufacturer: Vishay-Dale; CompType: Resistor; Res_ohm: 4990; Value_Code: 4k99; Tolerance_%: 1; Power_W: 0.1; VDC_V: 75; TempCo: 100 ppm/C; EIA_Code: E96; U/M: EA
R19 = CRCW080539K0JNEA: RES, 39k ohm, 5%, 0.125W, 0805; Manufacturer: Vishay-Dale; CompType: Resistor; Res_ohm: 39000; Value_Code: 39k0; Tolerance_%: 5; Power_W: 0.125; VDC_V: 150; TempCo: 200 ppm/C; EIA_Code: E24; U/M: EA
R20 = CRCW12063R30JNEA: RES, 3.3 ohm, 5%, 0.25W, 1206; Manufacturer: Vishay-Dale; CompType: Resistor; Value_Code: 3R30; Tolerance_%: 5; Power_W: 0.25; VDC_V: 200; TempCo: 200 ppm/C; EIA_Code: E24; U/M: EA
R21 = CRCW080520R0JNEA: RES, 20 ohm, 5%, 0.125W, 0805; Manufacturer: Vishay-Dale; CompType: Resistor; Value_Code: 20R0; Tolerance_%: 5; Power_W: 0.125; VDC_V: 150; TempCo: 200 ppm/C; EIA_Code: E24; U/M: EA
R22 = CRCW060327K4FKEA: RES, 27.4k ohm, 1%, 0.1W, 0603; Manufacturer: Vishay-Dale; CompType: Resistor; Res_ohm: 27400; Value_Code: 27k4; Tolerance_%: 1; Power_W: 0.1; VDC_V: 75; TempCo: 100 ppm/C; EIA_Code: E96; U/M: EA
R23 = ERJ-3GEY0R00V: RES, 0 ohm, 5%, 0.1W, 0603; Manufacturer: Panasonic; CompType: Resistor; Value_Code: 0000; Tolerance_%: 5; Power_W: 0.1; VDC_V: 50; TempCo: 600 ppm/C; EIA_Code: E24; U/M: EA
R25 = CRCW0603681RFKEA: RES, 681 ohm, 1%, 0.1W, 0603; Manufacturer: Vishay-Dale; CompType: Resistor; Value_Code: 681R; Tolerance_%: 1; Power_W: 0.1; VDC_V: 75; TempCo: 100 ppm/C; EIA_Code: E96; U/M: EA
R26 = CRCW060310K0FKEA: RES, 10.0k ohm, 1%, 0.1W, 0603; Manufacturer: Vishay-Dale; CompType: Resistor; Res_ohm: 10000; Value_Code: 10k0; Tolerance_%: 1; Power_W: 0.1; VDC_V: 75; TempCo: 100 ppm/C; EIA_Code: E96; U/M: EA
R27 R39 = CRCW06032K00FKEA: RES, 2.00k ohm, 1%, 0.1W, 0603; Manufacturer: Vishay-Dale; CompType: Resistor; Res_ohm: 2000; Value_Code: 2k00; Tolerance_%: 1; Power_W: 0.1; VDC_V: 75; TempCo: 100 ppm/C; EIA_Code: E96; U/M: EA
R28 = CRCW0603392KFKEA: RES, 392k ohm, 1%, 0.1W, 0603; Manufacturer: Vishay-Dale; CompType: Resistor; Res_ohm: 392000; Tolerance_%: 1; Power_W: 0.1; VDC_V: 75; TempCo: 100 ppm/C; EIA_Code: E96; U/M: EA
R29 R32 R38 = CRCW06031K00FKEA: RES, 1.00k ohm, 1%, 0.1W, 0603; Manufacturer: Vishay-Dale; CompType: Resistor; Res_ohm: 1000; Value_Code: 1k00; Tolerance_%: 1; Power_W: 0.1; VDC_V: 75; TempCo: 100 ppm/C; EIA_Code: E96; U/M: EA
R30 = ERJ-8RQF1R0V: RES, 0.5 ohm, 1%, 0.25W, 1206; Manufacturer: Panasonic; CompType: Resistor; Value_Code: 0R50; Tolerance_%: 1; Power_W: 0.25; TempCo: 200 ppm/C; EIA_Code: E96; U/M: EA
R31 = CRCW060344K2FKEA: RES, 44.2k ohm, 1%, 0.1W, 0603; Manufacturer: Vishay-Dale; CompType: Resistor; Res_ohm: 44200; Value_Code: 44k2; Tolerance_%: 1; Power_W: 0.1; VDC_V: 75; TempCo: 100 ppm/C; EIA_Code: E96; U/M: EA
R33 = CRCW060320K5FKEA: RES, 20.5k ohm, 1%, 0.1W, 0603; Manufacturer: Vishay-Dale; CompType: Resistor; Res_ohm: 20500; Value_Code: 20k5; Tolerance_%: 1; Power_W: 0.1; VDC_V: 75; TempCo: 100 ppm/C; EIA_Code: E96; U/M: EA
R34 = CRCW060359K0FKEA: RES, 59.0k ohm, 1%, 0.1W, 0603; Manufacturer: Vishay-Dale; CompType: Resistor; Res_ohm: 59000; Value_Code: 59k0; Tolerance_%: 1; Power_W: 0.1; VDC_V: 75; TempCo: 100 ppm/C; EIA_Code: E96; U/M: EA
R35 = CRCW060380K6FKEA: RES, 80.6k ohm, 1%, 0.1W, 0603; Manufacturer: Vishay-Dale; CompType: Resistor; Res_ohm: 80600; Value_Code: 80k6; Tolerance_%: 1; Power_W: 0.1; VDC_V: 75; TempCo: 100 ppm/C; EIA_Code: E96; U/M: EA
R36 = CRCW060390R9FKEA: RES, 90.9 ohm, 1%, 0.1W, 0603; Manufacturer: Vishay-Dale; CompType: Resistor; Value_Code: 90R9; Tolerance_%: 1; Power_W: 0.1; VDC_V: 75; TempCo: 100 ppm/C; EIA_Code: E96; U/M: EA
R37 = CRCW060314K3FKEA: RES, 14.3k ohm, 1%, 0.1W, 0603; Manufacturer: Vishay-Dale; CompType: Resistor; Res_ohm: 14300; Value_Code: 14k3; Tolerance_%: 1; Power_W: 0.1; VDC_V: 75; TempCo: 100 ppm/C; EIA_Code: E96; U/M: EA
T2 = PA6340-AL: Transformer, 142uH, SMT; Manufacturer: Coilcraft; SymbolCreator: a0799628; DCR_Ohm: 0.23; LeakageL: 1.5 uH; U/M: EA
U1 = TPS23753APW: IEEE 802.3 PoE INTERFACE AND CONVERTER CONTROLLER WITH ENHANCED ESD IMMUNITY, PW0014A; Alternate Manufacturer: None; Manufacturer: Texas Instruments; SymbolCreator: a0412235; CompType: IC; U/M: EA
U2 = HMHA2801A: Optocoupler, 3.75kV RMS, SMT; Manufacturer: Fairchild Semiconductor; U/M: EA
U3 = TLV431AIDBV: LOW-VOLTAGE ADJUSTABLE PRECISION SHUNT REGULATOR, DBV0005A; Alternate Manufacturer: None; Manufacturer: Texas Instruments; SymbolCreator: a0411947; CompType: IC; U/M: EA

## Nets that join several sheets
PWRGND: PMP9175_RevA_SH1 (C3.2 L2.2), PMP9175_RevA_SH2 (14 pins)
AUX: PMP9175_RevA_SH1 (C3.1 D1.2 L1.2), PMP9175_RevA_SH2 (R28.2)
VDD: PMP9175_RevA_SH1 (C9.1 D1.1 L3.2), PMP9175_RevA_SH2 (7 pins)
VSS: PMP9175_RevA_SH1 (C9.2 L4.2), PMP9175_RevA_SH2 (C35.2 D16.2 R36.1 U1.7)

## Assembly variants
001: not fitted FID1 FID2 FID3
